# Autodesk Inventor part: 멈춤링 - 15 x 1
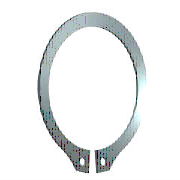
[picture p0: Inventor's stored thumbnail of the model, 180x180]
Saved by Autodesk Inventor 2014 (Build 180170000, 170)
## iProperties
Created: 2015-09
Part Number: 멈춤링 - 15 x 1
Material: 강, 연강
Description: 리테이닝 링(C형)
Document SubType Name: Modeling
Standard: KS B 1336
Designer: mm
Standards Organization: KS
Language: ko-KR
Size Designation: 15 x 1
Categories: <MemberInstance><Categories><Category DisplayName="샤프트 부품" InternalName="7f7aeb1f-a693-4053-b835-cee3144e0d98" Mnemonic="SHFT"><Category DisplayName="써클립" Inter
Density: 1 g/cm^3
Appearance: Glossy - Black
IsCustomPart: 1
Author: mduedu
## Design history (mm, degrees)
sketch "스케치1"
  geometry: L1 (-6, 0)-(6, 0) reference; L2 (0, 20.189)-(0, -80.536) reference; L3 (-48.09, 0)-(48.09, 0) reference; L4 (-0.425, -14.637)-(-0.425, -18.137); L5 (-0.425, -6.54)-(-0.425, -13.29); L6 (-2.795, 2.1)-(3.672, 2.1); L7 (0.425, -6.54)-(0.425, -13.29); L8 (0.425, -14.637)-(0.425, -18.137); C1 r 0.85 at (-1.7, -16.283); C2 r 0.85 at (1.7, -16.283); A1 r 7.15 centre (0, -7.5) between (0.425, -14.637) and (-0.425, -14.637); A2 r 9.075 centre (0, -6.975) between (4.291, -14.971) and (-4.291, -14.971); A3 r 10.646 centre (0, -7.5) between (-2.023, -17.952) and (-0.425, -18.137); A4 r 1.7 centre (-1.7, -16.283) between (-3.397, -16.376) and (-2.023, -17.952); A5 r 1.7 centre (-5.095, -16.469) between (-3.397, -16.376) and (-4.291, -14.971); A6 r 1.7 centre (5.095, -16.469) between (4.291, -14.971) and (3.397, -16.376); A7 r 1.7 centre (1.7, -16.283) between (2.023, -17.952) and (3.397, -16.376); A8 r 10.646 centre (0, -7.5) between (0.425, -18.137) and (2.023, -17.952)
  constraints: 16 point on circle, 12 end point, 10 centre point, 9 symmetric about line, 5 point on line, 4 tangent, 3 coincident, 2 horizontal, 1 perpendicular, 1 vertical, 5 other
  dimensions: "d0" = 14.3 diameter of A1 (= ND); "d1" = 3.5 distance of L4.end L4.start (= SRB2); "d6" = 0.425 distance between parallel lines of L2 L5 (= 0.25 x SD5); "d7" = 2.1 distance between parallel lines of L6 L3 (= SRB1); "d8" = 0.525 distance of A1.centre A2.centre (= 0.25 x SRB1); "d9" = 1.7 radius of A4 (= SD5); "d10" = 1.7 radius of A5 (= SD5); "d11" = 1.275 distance from line of L4 A4.centre (= 0.75 x SD5); "d12" = 1.7 diameter of C1 (= SD5); "d13" = 1.7 diameter of C2 (= SD5); "d14" = 7.5 distance from line of A1.centre L1 (= 0.5 x WD)
extrude "본체" new body sketch "스케치1" distance "d2" = 1 (= SD); taper "d3" = 0 deg
workaxis "Work Axis1"
workplane "Work Plane1"
body "Solid1"
other parameters: "WD" = 15 (= WDMIN) [user parameter; used in 1 equation term], "SD" = 1 [user parameter; used in 1 equation term], "SRB1" = 2.1 [user parameter; used in 2 equation terms], "ND" = 14.3 [user parameter; used in 1 equation term], "SRB2" = 3.5 [user parameter; used in 1 equation term], "SD5" = 1.7 [user parameter; used in 6 equation terms], "d15" = 0, "d16" = 0, "d17" = 0, "d41" = 0, "d42" = 0, "WDMIN" = 15 [user parameter; used in 1 equation term], "SD3" = 13.8 [user parameter], "WDMAX" = 16 [user parameter]
